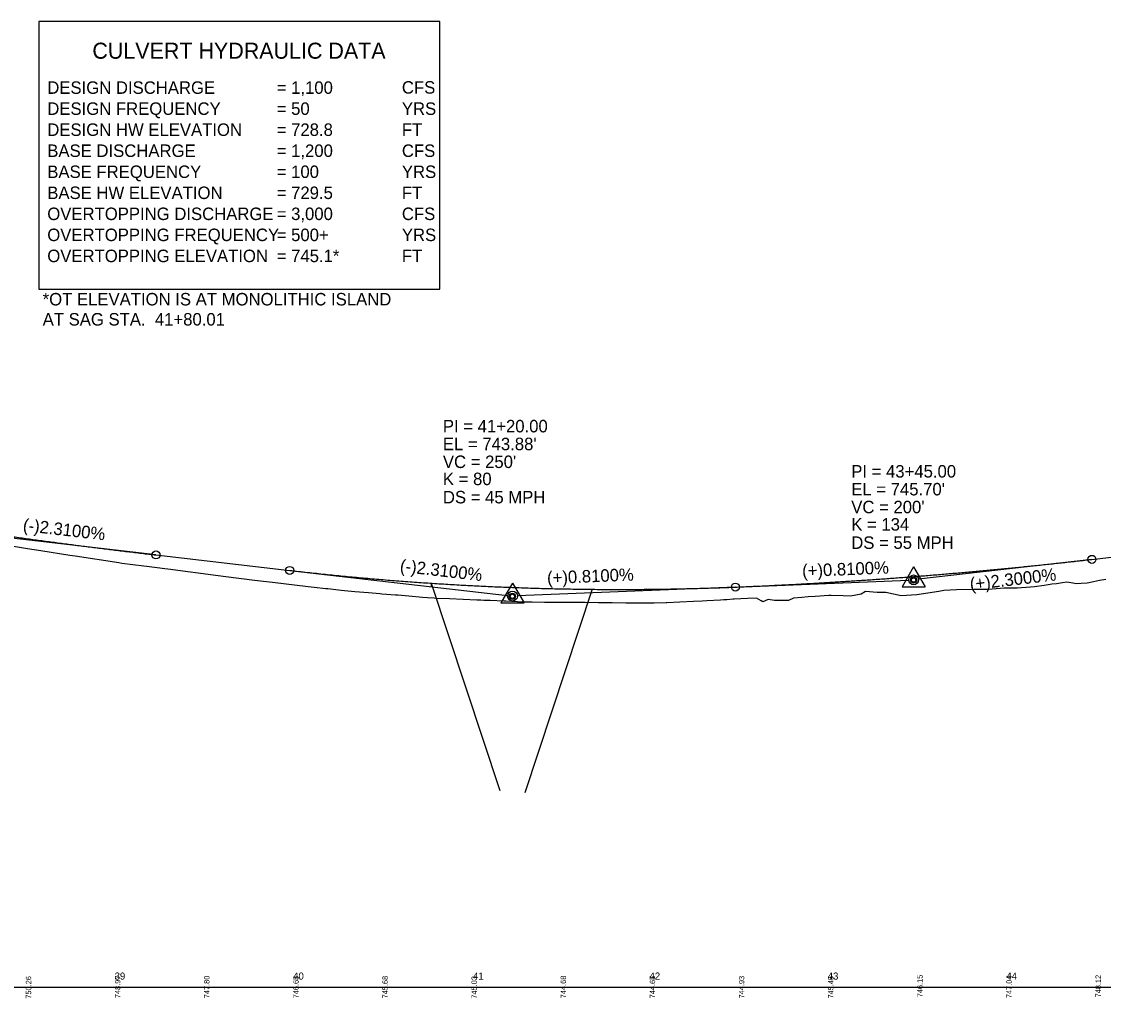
# Model space of a CAD drawing. Extents: x 1554255 to 1803987, y 659549 to 692876.
# Drawn here: x 1557638 to 1558245, y 692256 to 692804 of the extents above; entities that cross this region are included whole.
import ezdxf

# ---------------------------------------------------------------- set-up
doc = ezdxf.new("R2010")
doc.units = 0
for name, color, linetype in [('Default', 7, 'Continuous'), ('Exist Profile Cell', 7, 'Continuous'), ('Exist Vertical Profile Ground Line', 7, 'Continuous'), ('Prop Grid Mask', 7, 'Continuous'), ('Prop PFL Culvert Hydraulic Data Label CELL', 7, 'Continuous'), ('Prop PFL VPI Symbol CELL', 7, 'Continuous'), ('Prop Vertical Profile Curve Label', 7, 'Continuous'), ('Prop Vertical Profile Grade', 7, 'Continuous'), ('Prop Vertical Profile Grade Label', 7, 'Continuous'), ('Prop Vertical Profile Strip Grade', 7, 'Continuous'), ('Prop VPI Label', 7, 'Continuous'), ('Scratch_Level_3', 7, 'Continuous')]:
    doc.layers.add(name, color=color, linetype=linetype)

msp = doc.modelspace()

# ---------------------------------------------------------------- linework, layer by layer
at = {"layer": 'Exist Profile Cell'}
msp.add_line((1554793.69, 692261.88), (1561762.5, 692261.88), dxfattribs=at)
at = {"layer": 'Exist Vertical Profile Ground Line'}
for p, q in [((1557641.64, 692507.84), (1557619.17, 692511.38)), ((1557649.15, 692506.63), (1557641.64, 692507.84)), ((1557665.35, 692504.08), (1557649.15, 692506.63)), ((1557668.45, 692503.58), (1557665.35, 692504.08)), ((1557692.94, 692499.86), (1557668.45, 692503.58)), ((1557694.62, 692499.63), (1557692.94, 692499.86)), ((1557706.9, 692498.15), (1557694.62, 692499.63)), ((1557708.48, 692497.95), (1557706.9, 692498.15)), ((1557718.65, 692496.56), (1557708.48, 692497.95)), ((1557720.35, 692496.33), (1557718.65, 692496.56)), ((1557748.65, 692492.64), (1557720.35, 692496.33)), ((1557752.84, 692492.05), (1557748.65, 692492.64)), ((1557768.96, 692489.94), (1557752.84, 692492.05)), ((1557779.04, 692488.83), (1557768.96, 692489.94)), ((1557799, 692486.47), (1557779.04, 692488.83)), ((1557802.45, 692486.1), (1557799, 692486.47)), ((1557808.9, 692485.4), (1557802.45, 692486.1)), ((1557810.05, 692485.27), (1557808.9, 692485.4)), ((1558189.55, 692485.77), (1558180.49, 692484.94)), ((1558196.77, 692485.74), (1558189.55, 692485.77)), ((1558204.2, 692486.25), (1558196.77, 692485.74)), ((1558206.54, 692486.41), (1558204.2, 692486.25)), ((1558211.86, 692487.24), (1558206.54, 692486.41)), ((1558215.32, 692487.77), (1558211.86, 692487.24)), ((1558216.19, 692487.91), (1558215.32, 692487.77)), ((1558218.78, 692488.24), (1558216.19, 692487.91)), ((1558222.25, 692488.68), (1558218.78, 692488.24)), ((1558224.66, 692488.99), (1558222.25, 692488.68)), ((1558225.71, 692488.84), (1558224.66, 692488.99)), ((1558229.17, 692488.34), (1558225.71, 692488.84)), ((1558230.16, 692488.2), (1558229.17, 692488.34)), ((1558232.64, 692488.33), (1558230.16, 692488.2)), ((1558236.1, 692488.55), (1558232.64, 692488.33)), ((1558239.56, 692489.24), (1558236.1, 692488.55)), ((1558243.02, 692489.95), (1558239.56, 692489.24)), ((1558246.49, 692490.65), (1558243.02, 692489.95)), ((1557817.64, 692484.38), (1557810.05, 692485.27)), ((1557819.4, 692484.18), (1557817.64, 692484.38)), ((1557825.24, 692483.68), (1557819.4, 692484.18)), ((1557832.84, 692483.05), (1557825.24, 692483.68)), ((1557839.29, 692482.51), (1557832.84, 692483.05)), ((1557840.43, 692482.42), (1557839.29, 692482.51)), ((1557848.03, 692481.82), (1557840.43, 692482.42)), ((1557849.42, 692481.71), (1557848.03, 692481.82)), ((1557855.62, 692481.19), (1557849.42, 692481.71)), ((1557863.22, 692480.55), (1557855.62, 692481.19)), ((1557866.09, 692480.31), (1557863.22, 692480.55)), ((1557869.83, 692480.02), (1557866.09, 692480.31)), ((1557870.82, 692479.98), (1557869.83, 692480.02)), ((1557878.41, 692479.66), (1557870.82, 692479.98)), ((1557886.01, 692479.35), (1557878.41, 692479.66)), ((1557893.61, 692479.04), (1557886.01, 692479.35)), ((1558037.4, 692479.57), (1558033.99, 692479.11)), ((1558037.94, 692479.59), (1558037.4, 692479.57)), ((1558045.53, 692479.9), (1558037.94, 692479.59)), ((1558050.63, 692480.11), (1558045.53, 692479.9)), ((1558053.13, 692478.68), (1558050.63, 692480.11)), ((1558057.04, 692479.35), (1558054.12, 692478.12)), ((1558060.73, 692478.88), (1558057.04, 692479.35)), ((1558071.35, 692480.19), (1558068.49, 692478.73)), ((1558075.92, 692480.55), (1558071.35, 692480.19)), ((1558079.58, 692480.84), (1558075.92, 692480.55)), ((1558083.51, 692481.08), (1558079.58, 692480.84)), ((1558091.11, 692481.54), (1558083.51, 692481.08)), ((1558092.5, 692481.63), (1558091.11, 692481.54)), ((1558099.18, 692481.46), (1558092.5, 692481.63)), ((1558103.18, 692481.24), (1558099.18, 692481.46)), ((1558109.22, 692482.3), (1558103.18, 692481.24)), ((1558111.63, 692483.76), (1558109.22, 692482.3)), ((1558118.15, 692483.27), (1558111.63, 692483.76)), ((1558123.14, 692483.2), (1558118.15, 692483.27)), ((1558131.73, 692481.37), (1558123.14, 692483.2)), ((1558140.52, 692481.89), (1558131.73, 692481.37)), ((1558152.75, 692483.77), (1558140.52, 692481.89)), ((1558155.56, 692484.46), (1558152.75, 692483.77)), ((1558162.68, 692484.86), (1558155.56, 692484.46)), ((1558172.63, 692484.95), (1558162.68, 692484.86)), ((1558180.49, 692484.94), (1558172.63, 692484.95)), ((1557895.94, 692478.94), (1557893.61, 692479.04)), ((1557897.53, 692478.88), (1557895.94, 692478.94)), ((1557899.9, 692478.77), (1557897.53, 692478.88)), ((1557901.2, 692478.71), (1557899.9, 692478.77)), ((1557908.8, 692478.39), (1557901.2, 692478.71)), ((1557910.01, 692478.34), (1557908.8, 692478.39)), ((1557916.4, 692478.04), (1557910.01, 692478.34)), ((1557919.68, 692477.89), (1557916.4, 692478.04)), ((1557923.99, 692477.81), (1557919.68, 692477.89)), ((1557924.77, 692477.79), (1557923.99, 692477.81)), ((1557931.59, 692477.74), (1557924.77, 692477.79)), ((1557935.86, 692477.7), (1557931.59, 692477.74)), ((1557939.18, 692477.68), (1557935.86, 692477.7)), ((1557946.78, 692477.64), (1557939.18, 692477.68)), ((1557949.86, 692477.63), (1557946.78, 692477.64)), ((1557954.38, 692477.61), (1557949.86, 692477.63)), ((1557961.97, 692477.57), (1557954.38, 692477.61)), ((1557963.92, 692477.56), (1557961.97, 692477.57)), ((1557969.62, 692477.55), (1557963.92, 692477.56)), ((1557977.17, 692477.39), (1557969.62, 692477.55)), ((1557983.32, 692477.26), (1557977.17, 692477.39)), ((1557984.76, 692477.25), (1557983.32, 692477.26)), ((1557992.36, 692477.22), (1557984.76, 692477.25)), ((1557993.08, 692477.22), (1557992.36, 692477.22)), ((1557999.96, 692477.47), (1557993.08, 692477.22)), ((1558000.26, 692477.48), (1557999.96, 692477.47)), ((1558007.55, 692477.82), (1558000.26, 692477.48)), ((1558015.15, 692478.17), (1558007.55, 692477.82)), ((1558019.98, 692478.4), (1558015.15, 692478.17)), ((1558022.74, 692478.53), (1558019.98, 692478.4)), ((1558030.38, 692478.9), (1558022.74, 692478.53)), ((1558032.28, 692479.19), (1558030.38, 692478.9)), ((1558033.99, 692479.11), (1558032.28, 692479.19)), ((1558054.12, 692478.12), (1558053.13, 692478.68)), ((1558061.64, 692478.76), (1558060.73, 692478.88)), ((1558068.49, 692478.73), (1558061.64, 692478.76))]:
    msp.add_line(p, q, dxfattribs=at)
at = {"layer": 'Prop Grid Mask'}
msp.add_lwpolyline([(1557647.9, 692653.5), (1557872.9, 692653.5), (1557872.9, 692803.5), (1557647.9, 692803.5)], close=True, dxfattribs=at)
at = {"layer": 'Prop PFL VPI Symbol CELL'}
for p, q in [((1558138.64, 692497.73), (1558132.19, 692486.53)), ((1558138.64, 692497.73), (1558145.14, 692486.53)), ((1557913.64, 692488.61), (1557907.19, 692477.41)), ((1557913.64, 692488.61), (1557920.14, 692477.41)), ((1558132.19, 692486.53), (1558145.14, 692486.53)), ((1557907.19, 692477.41), (1557920.14, 692477.41))]:
    msp.add_line(p, q, dxfattribs=at)
for centre, radius in [((1558138.65, 692490.25), 1.75), ((1558138.65, 692490.25), 1.2), ((1557913.65, 692481.13), 1.75), ((1557913.65, 692481.13), 1.2)]:
    msp.add_circle(centre, radius, dxfattribs=at)
at = {"layer": 'Prop Vertical Profile Curve Label'}
for centre in [(1557713.69, 692504.36), (1558238.69, 692501.88), (1557788.69, 692495.7), (1558038.69, 692486.33), (1558038.69, 692486.33)]:
    msp.add_circle(centre, 2.25, dxfattribs=at)
at = {"layer": 'Prop Vertical Profile Grade'}
for p, q in [((1557713.69, 692504.36), (1557788.69, 692495.7)), ((1558238.69, 692501.88), (1558288.69, 692507.63))]:
    msp.add_line(p, q, dxfattribs=at)
for points in [[(1557513.69, 692533.43), (1557517.69, 692532.74), (1557521.69, 692532.04), (1557525.69, 692531.35), (1557529.69, 692530.67), (1557533.69, 692529.99), (1557537.69, 692529.32), (1557541.69, 692528.65), (1557545.69, 692527.98), (1557549.69, 692527.32), (1557553.69, 692526.67), (1557557.69, 692526.01), (1557561.69, 692525.37), (1557565.69, 692524.73), (1557569.69, 692524.09), (1557573.69, 692523.46), (1557577.69, 692522.83), (1557581.69, 692522.21), (1557585.69, 692521.59), (1557589.69, 692520.98), (1557593.69, 692520.37), (1557597.69, 692519.77), (1557601.69, 692519.17), (1557605.69, 692518.58), (1557609.69, 692517.99), (1557613.69, 692517.41), (1557617.69, 692516.83), (1557621.69, 692516.25), (1557625.69, 692515.68), (1557629.69, 692515.12), (1557633.69, 692514.56), (1557637.69, 692514), (1557641.69, 692513.45), (1557645.69, 692512.91), (1557649.69, 692512.37), (1557653.69, 692511.83), (1557657.69, 692511.3), (1557661.69, 692510.77), (1557665.69, 692510.25), (1557669.69, 692509.74), (1557673.69, 692509.22), (1557677.69, 692508.72), (1557681.69, 692508.21), (1557685.69, 692507.72), (1557689.69, 692507.22), (1557693.69, 692506.73), (1557697.69, 692506.25), (1557701.69, 692505.77), (1557705.69, 692505.3), (1557709.69, 692504.83), (1557713.69, 692504.36)], [(1558038.69, 692486.33), (1558042.69, 692486.49), (1558046.69, 692486.66), (1558050.69, 692486.84), (1558054.69, 692487.02), (1558058.69, 692487.21), (1558062.69, 692487.41), (1558066.69, 692487.61), (1558070.69, 692487.81), (1558074.69, 692488.03), (1558078.69, 692488.25), (1558082.69, 692488.47), (1558086.69, 692488.7), (1558090.69, 692488.94), (1558094.69, 692489.18), (1558098.69, 692489.43), (1558102.69, 692489.68), (1558106.69, 692489.94), (1558110.69, 692490.21), (1558114.69, 692490.48), (1558118.69, 692490.76), (1558122.69, 692491.04), (1558126.69, 692491.33), (1558130.69, 692491.63), (1558134.69, 692491.93), (1558138.69, 692492.24), (1558142.69, 692492.55), (1558146.69, 692492.87), (1558150.69, 692493.2), (1558154.69, 692493.53), (1558158.69, 692493.87), (1558162.69, 692494.21), (1558166.69, 692494.56), (1558170.69, 692494.92), (1558174.69, 692495.28), (1558178.69, 692495.65), (1558182.69, 692496.02), (1558186.69, 692496.4), (1558190.69, 692496.79), (1558194.69, 692497.18), (1558198.69, 692497.58), (1558202.69, 692497.98), (1558206.69, 692498.39), (1558210.69, 692498.8), (1558214.69, 692499.22), (1558218.69, 692499.65), (1558222.69, 692500.08), (1558226.69, 692500.52), (1558230.69, 692500.97), (1558234.69, 692501.42), (1558238.69, 692501.88)], [(1557788.69, 692495.7), (1557793.69, 692495.13), (1557798.69, 692494.58), (1557803.69, 692494.04), (1557808.69, 692493.52), (1557813.69, 692493.01), (1557818.69, 692492.52), (1557823.69, 692492.04), (1557828.69, 692491.58), (1557833.69, 692491.14), (1557838.69, 692490.71), (1557843.69, 692490.29), (1557848.69, 692489.9), (1557853.69, 692489.51), (1557858.69, 692489.15), (1557863.69, 692488.79), (1557868.69, 692488.46), (1557873.69, 692488.14), (1557878.69, 692487.83), (1557883.69, 692487.55), (1557888.69, 692487.27), (1557893.69, 692487.01), (1557898.69, 692486.77), (1557903.69, 692486.55), (1557908.69, 692486.34), (1557913.69, 692486.14), (1557918.69, 692485.96), (1557923.69, 692485.8), (1557928.69, 692485.65), (1557933.69, 692485.51), (1557938.69, 692485.4), (1557943.69, 692485.3), (1557948.69, 692485.21), (1557953.69, 692485.14), (1557958.69, 692485.08), (1557963.69, 692485.04), (1557968.69, 692485.02), (1557973.69, 692485.01), (1557978.69, 692485.02), (1557983.69, 692485.04), (1557988.69, 692485.08), (1557993.69, 692485.14), (1557998.69, 692485.21), (1558003.69, 692485.29), (1558008.69, 692485.39), (1558013.69, 692485.51), (1558018.69, 692485.64), (1558023.69, 692485.79), (1558028.69, 692485.95), (1558033.69, 692486.13), (1558038.69, 692486.33)]]:
    msp.add_spline(points, degree=3, dxfattribs=at)
at = {"layer": 'Prop VPI Label'}
for p, q in [((1557713.69, 692504.36), (1557616.42, 692515.6)), ((1558238.69, 692501.88), (1558141.42, 692490.69)), ((1557788.69, 692495.7), (1557910.96, 692481.58)), ((1558038.69, 692486.33), (1557916.44, 692481.38)), ((1558038.69, 692486.33), (1558135.94, 692490.27))]:
    msp.add_line(p, q, dxfattribs=at)
for centre in [(1558138.69, 692490.38), (1557913.69, 692481.26)]:
    msp.add_circle(centre, 2.75, dxfattribs=at)
at = {"layer": 'Scratch_Level_3'}
for p, q in [((1557868.07, 692488.5), (1557906.59, 692372.14)), ((1557868.07, 692488.5), (1557868.07, 692486.8)), ((1557958.39, 692485.09), (1557920.59, 692370.88))]:
    msp.add_line(p, q, dxfattribs=at)

# ---------------------------------------------------------------- texts
at = {"layer": 'Default'}
for s, p in [('39', (1557690.51, 692266.13)), ('40', (1557790.66, 692266.13)), ('41', (1557891.55, 692266.13)), ('42', (1557990.55, 692266.13)), ('43', (1558090.52, 692266.13)), ('44', (1558190.73, 692266.13))]:
    msp.add_text(s, height=4, dxfattribs=at).set_placement(p)
at = {"layer": 'Prop PFL Culvert Hydraulic Data Label CELL'}
for s, height, p in [('CULVERT HYDRAULIC DATA', 9, (1557678, 692782.7)), ('DESIGN DISCHARGE', 6.9999, (1557652.73, 692763)), ('= 1,100   ', 7, (1557781.43, 692763)), ('CFS', 7, (1557851.63, 692763.1)), ('DESIGN FREQUENCY', 6.9999, (1557652.73, 692751.2)), ('= 50 ', 7, (1557781.43, 692751.2)), ('YRS', 7, (1557851.63, 692751.2)), ('DESIGN HW ELEVATION', 6.9999, (1557652.73, 692739.4)), ('= 728.8   ', 7, (1557781.43, 692739.4)), ('FT', 7, (1557851.63, 692739.4)), ('BASE DISCHARGE', 6.9999, (1557652.73, 692727.6)), ('= 1,200   ', 7, (1557781.43, 692727.6)), ('CFS', 7, (1557851.63, 692727.6)), ('BASE FREQUENCY', 6.9999, (1557652.73, 692715.8)), ('= 100', 7, (1557781.43, 692715.8)), ('YRS', 7, (1557851.63, 692715.8)), ('BASE HW ELEVATION', 6.9999, (1557652.73, 692704)), ('= 729.5   ', 7, (1557781.43, 692704)), ('FT', 7, (1557851.63, 692704)), ('OVERTOPPING DISCHARGE', 6.9999, (1557652.73, 692692.2)), ('= 3,000   ', 7, (1557781.43, 692692.2)), ('CFS', 7, (1557851.63, 692692.2)), ('OVERTOPPING FREQUENCY', 6.9999, (1557652.73, 692680.4)), ('= 500+', 7, (1557781.43, 692680.4)), ('YRS', 7, (1557851.63, 692680.4)), ('OVERTOPPING ELEVATION', 6.9999, (1557652.73, 692668.6)), ('= 745.1*  ', 7, (1557781.43, 692668.6)), ('FT', 7, (1557851.63, 692668.6)), ('*OT ELEVATION IS AT MONOLITHIC ISLAND', 6.9999, (1557650.14, 692644.31)), ('AT SAG STA.  41+80.01', 6.9999, (1557650.14, 692633.04))]:
    msp.add_text(s, height=height, dxfattribs=at).set_placement(p)
at = {"layer": 'Prop Vertical Profile Curve Label'}
for s, p in [("VC = 250'", (1557874.64, 692553.11)), ('K = 80', (1557874.64, 692543.52)), ('DS = 45 MPH', (1557874.64, 692533.28)), ("VC = 200'", (1558103.69, 692527.75)), ('K = 134', (1558103.69, 692518)), ('DS = 55 MPH', (1558103.69, 692507.75))]:
    msp.add_text(s, height=7, dxfattribs=at).set_placement(p)
at = {"layer": 'Prop Vertical Profile Grade Label'}
for s, rotation, p in [('(-)2.3100%', 353.41153, (1557638.82, 692517.81)), ('(-)2.3100%', 353.41153, (1557850.29, 692494.95)), ('(+)0.8100%', 2.31921, (1558076.28, 692491.96)), ('(+)0.8100%', 2.31921, (1557933.2, 692488.01)), ('(+)2.3000%', 6.5602, (1558170.62, 692484.51))]:
    msp.add_text(s, height=7, rotation=rotation, dxfattribs=at).set_placement(p)
at = {"layer": 'Prop Vertical Profile Strip Grade'}
for s, p in [('750.26', (1557643.69, 692255.43)), ('748.97', (1557693.69, 692255.74)), ('747.80', (1557743.69, 692255.69)), ('746.65', (1557793.69, 692255.63)), ('745.68', (1557843.69, 692255.58)), ('745.03', (1557893.69, 692255.42)), ('744.68', (1557943.69, 692255.68)), ('744.65', (1557993.69, 692255.63)), ('744.93', (1558043.69, 692255.56)), ('745.45', (1558093.69, 692255.54)), ('746.15', (1558143.69, 692256.24)), ('747.04', (1558193.69, 692255.74)), ('748.12', (1558243.69, 692256.15))]:
    msp.add_text(s, height=3, rotation=90, dxfattribs=at).set_placement(p)
at = {"layer": 'Prop VPI Label'}
for s, p in [('PI = 41+20.00', (1557874.64, 692573.11)), ("EL = 743.88'", (1557874.64, 692563.11)), ('PI = 43+45.00', (1558103.69, 692547.75)), ("EL = 745.70'", (1558103.69, 692537.75))]:
    msp.add_text(s, height=7, dxfattribs=at).set_placement(p)

doc.saveas('drawing.dxf')
